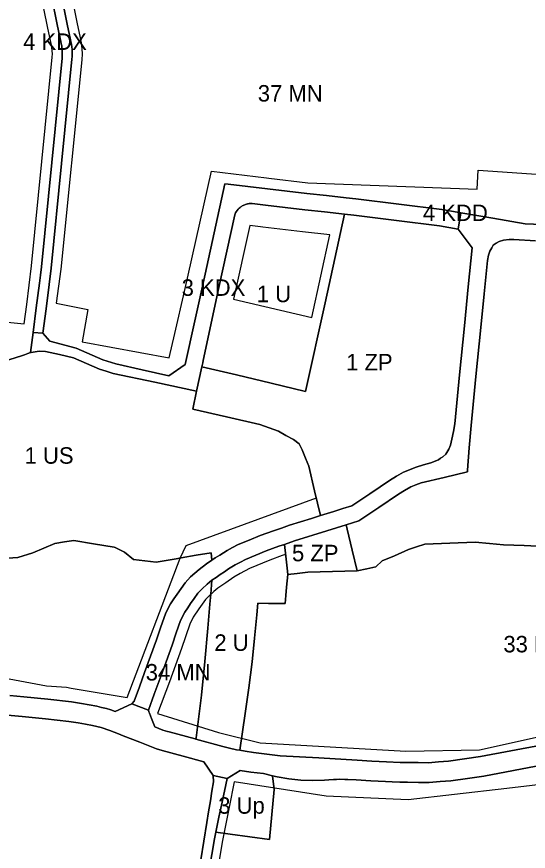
# Model space of a CAD drawing. Extents: x 7423432 to 7425824, y 5537848 to 5539677.
# Drawn here: x 7424531 to 7424841, y 5538619 to 5539125 of the extents above; entities that cross this region are included whole.
import ezdxf

# ---------------------------------------------------------------- set-up
doc = ezdxf.new("R2010")
doc.units = 0
for name, color, linetype in [('linie_rozgraniczajace', 7, 'Continuous'), ('linie_zabudowy_nieprzekraczalne', 7, 'Continuous'), ('oznaczenia_przeznaczen', 7, 'Continuous')]:
    doc.layers.add(name, color=color, linetype=linetype)

msp = doc.modelspace()

# ---------------------------------------------------------------- linework, layer by layer
at = {"layer": 'linie_rozgraniczajace'}
for points in [[(7424557.72, 5539139.78), (7424561.59, 5539120.6), (7424563.62, 5539111.18), (7424564.15, 5539108.31), (7424564.31, 5539106.77), (7424564.48, 5539105.23), (7424564.54, 5539103.9), (7424564.59, 5539102.57), (7424564.52, 5539100.96), (7424564.45, 5539099.35), (7424558.13, 5539035.99), (7424551.8, 5538972.62), (7424550.63, 5538962.66), (7424548.74, 5538947.91), (7424546.85, 5538933.16), (7424540.84, 5538933.51), (7424542.76, 5538948.45), (7424544.68, 5538963.39), (7424545.26, 5538968.36), (7424545.85, 5538973.33), (7424558.49, 5539100.07), (7424558.59, 5539102.66), (7424558.49, 5539104.79), (7424558.21, 5539107.44), (7424557.97, 5539108.72), (7424557.73, 5539110), (7424555.72, 5539119.38), (7424551.85, 5539138.56)], [(7424551.85, 5539138.56), (7424555.72, 5539119.38), (7424557.73, 5539110), (7424557.97, 5539108.72), (7424558.21, 5539107.44), (7424558.49, 5539104.79), (7424558.59, 5539102.66), (7424558.49, 5539100.07), (7424545.85, 5538973.33), (7424545.26, 5538968.36)], [(7424546.85, 5538933.16), (7424548.74, 5538947.91), (7424550.63, 5538962.66), (7424551.8, 5538972.62), (7424558.13, 5539035.99), (7424564.45, 5539099.35), (7424564.52, 5539100.96), (7424564.59, 5539102.57), (7424564.54, 5539103.9), (7424564.48, 5539105.23), (7424564.31, 5539106.77), (7424564.15, 5539108.31), (7424563.62, 5539111.18), (7424561.59, 5539120.6), (7424557.72, 5539139.78)], [(7424849.72, 5538998.98), (7424839.61, 5538999.48), (7424820.03, 5539002.8), (7424800.46, 5539006.12), (7424794.76, 5539007.09), (7424789.05, 5539008.06), (7424762.88, 5539011.29), (7424736.7, 5539014.52), (7424730.84, 5539015.25), (7424718.91, 5539016.56), (7424706.98, 5539017.88), (7424683.15, 5539020.68), (7424671.24, 5539022.11), (7424659.33, 5539023.54), (7424657.23, 5539023.79), (7424645.24, 5538968.93), (7424633.26, 5538914.07), (7424623.23, 5538907.09)], [(7424804.53, 5538848.9), (7424790.47, 5538845.55), (7424776.41, 5538842.19), (7424773.26, 5538840.96), (7424770.12, 5538839.73), (7424766.36, 5538837.51), (7424762.6, 5538835.28), (7424750.65, 5538827.26), (7424738.7, 5538819.24), (7424730.99, 5538816.82), (7424719.15, 5538813.1), (7424699.59, 5538806.95), (7424693.42, 5538804.88), (7424690.07, 5538803.76), (7424686.19, 5538802.32), (7424682.31, 5538800.89), (7424676.03, 5538798.33), (7424669.75, 5538795.77), (7424666.68, 5538794.11), (7424663.61, 5538792.44), (7424661.55, 5538791.21), (7424659.5, 5538789.98), (7424656.99, 5538788.29), (7424654.48, 5538786.6), (7424651.93, 5538784.84), (7424649.39, 5538783.08), (7424646.59, 5538780.79), (7424643.52, 5538777.98), (7424640.88, 5538775.19), (7424638.62, 5538772.06), (7424636.47, 5538769.09), (7424634.7, 5538766.38), (7424632.93, 5538763.66), (7424630.37, 5538758.77), (7424627.79, 5538751.21), (7424625.25, 5538743.79), (7424621.59, 5538733.63), (7424617.97, 5538723.61), (7424614.39, 5538713.92), (7424610.81, 5538704.24), (7424600.85, 5538708.15), (7424602.22, 5538709.76), (7424605.4, 5538718.39), (7424608.57, 5538727.03), (7424612.17, 5538737), (7424615.77, 5538746.97), (7424618.46, 5538754.85), (7424621.16, 5538762.73), (7424622.72, 5538765.73), (7424624.29, 5538768.72), (7424626.26, 5538771.74), (7424628.22, 5538774.75), (7424630.7, 5538778.17), (7424633.17, 5538781.59), (7424636.5, 5538785.11), (7424641.7, 5538789.71), (7424646.06, 5538792.98), (7424649.39, 5538795.3), (7424651.45, 5538796.66), (7424654.13, 5538798.42), (7424658.66, 5538801.13), (7424661.99, 5538802.94), (7424665.32, 5538804.75), (7424672, 5538807.48), (7424678.69, 5538810.21), (7424682.72, 5538811.7), (7424686.75, 5538813.19), (7424691.62, 5538814.82), (7424696.5, 5538816.46), (7424709.95, 5538820.69), (7424715.41, 5538822.4), (7424723.4, 5538824.91), (7424728.86, 5538826.63), (7424734.33, 5538828.35), (7424739.76, 5538832), (7424745.18, 5538835.66), (7424751.48, 5538839.87), (7424757.26, 5538843.74), (7424761.49, 5538846.25), (7424765.72, 5538848.75), (7424773.41, 5538851.76), (7424777.9, 5538853.09), (7424782.39, 5538854.43), (7424786.87, 5538856.19), (7424788.28, 5538857.14), (7424789.68, 5538858.1), (7424791.42, 5538859.65), (7424793.33, 5538862.62), (7424794.25, 5538865), (7424795.16, 5538868.67), (7424795.98, 5538873.32), (7424796.79, 5538877.96), (7424799.74, 5538907.7), (7424802.69, 5538937.44), (7424805.04, 5538961.17), (7424807.39, 5538984.91), (7424799, 5538996.25), (7424800.46, 5539006.12), (7424820.03, 5539002.8), (7424839.61, 5538999.48)], [(7424839.61, 5538999.48), (7424849.72, 5538998.98)], [(7424851.33, 5538803.62), (7424838.93, 5538804.14), (7424826.52, 5538804.66), (7424817.83, 5538805.4), (7424809.13, 5538806.14), (7424793.85, 5538805.62), (7424778.58, 5538805.11), (7424773.68, 5538803.42), (7424768.78, 5538801.73), (7424760.22, 5538797.86), (7424752.7, 5538794.88), (7424748.9, 5538791.18), (7424743.37, 5538790), (7424737.5, 5538788.74), (7424734.55, 5538801.44), (7424731.61, 5538814.15), (7424730.99, 5538816.82), (7424738.7, 5538819.24), (7424750.65, 5538827.26), (7424762.6, 5538835.28), (7424766.36, 5538837.51), (7424770.12, 5538839.73), (7424773.26, 5538840.96), (7424776.41, 5538842.19), (7424790.47, 5538845.55), (7424804.53, 5538848.9), (7424804.53, 5538849.85), (7424805.64, 5538863.46), (7424806.75, 5538877.06), (7424809.69, 5538906.76), (7424812.64, 5538936.45), (7424814.66, 5538956.85), (7424816.68, 5538977.25), (7424817.35, 5538980.5), (7424818.13, 5538982.75), (7424819.28, 5538984.96), (7424820.24, 5538986.38), (7424821.95, 5538987.79), (7424823.76, 5538988.8), (7424826.49, 5538989.53), (7424829.85, 5538989.89), (7424831.25, 5538989.87), (7424832.64, 5538989.85), (7424845.95, 5538989.12)], [(7424845.95, 5538989.12), (7424832.64, 5538989.85), (7424831.25, 5538989.87), (7424829.85, 5538989.89), (7424826.49, 5538989.53), (7424823.76, 5538988.8), (7424821.95, 5538987.79), (7424820.24, 5538986.38), (7424819.28, 5538984.96), (7424818.13, 5538982.75), (7424817.35, 5538980.5), (7424816.68, 5538977.25), (7424814.66, 5538956.85), (7424812.64, 5538936.45), (7424809.69, 5538906.76), (7424806.75, 5538877.06), (7424805.64, 5538863.46), (7424804.53, 5538849.85), (7424804.53, 5538848.9)], [(7424545.26, 5538968.36), (7424544.68, 5538963.39), (7424542.76, 5538948.45), (7424540.84, 5538933.51), (7424539.27, 5538921.25), (7424537.6, 5538920.64), (7424535.58, 5538919.91), (7424533.84, 5538919.37), (7424518.78, 5538914.58)], [(7424623.23, 5538907.09), (7424607.13, 5538910.78), (7424591.03, 5538914.47), (7424583.19, 5538916.87), (7424567.01, 5538924.01), (7424551.05, 5538928.12), (7424546.85, 5538933.16)], [(7424518.78, 5538914.58), (7424533.84, 5538919.37), (7424535.58, 5538919.91), (7424537.6, 5538920.64), (7424539.27, 5538921.25), (7424539.62, 5538921.38), (7424544.6, 5538922.22), (7424548.43, 5538922.03), (7424556.92, 5538920.09), (7424565.42, 5538918.16), (7424573.26, 5538914.7), (7424581.1, 5538911.24), (7424585.29, 5538909.95), (7424589.48, 5538908.67), (7424614.78, 5538903.28), (7424640.08, 5538897.9), (7424637.89, 5538886.94), (7424658.18, 5538882.26), (7424678.47, 5538877.57), (7424689.8, 5538873.51), (7424694.37, 5538871.02), (7424698.95, 5538868.53), (7424702.29, 5538865.92), (7424704.22, 5538862.19), (7424706.19, 5538857.26), (7424708.16, 5538852.32), (7424711.78, 5538837.36), (7424715.41, 5538822.4), (7424709.95, 5538820.69), (7424696.5, 5538816.46), (7424691.62, 5538814.82), (7424686.75, 5538813.19), (7424682.72, 5538811.7), (7424678.69, 5538810.21), (7424672, 5538807.48), (7424665.32, 5538804.75), (7424661.99, 5538802.94), (7424658.66, 5538801.13), (7424654.13, 5538798.42), (7424651.45, 5538796.66), (7424649.39, 5538795.3), (7424648.95, 5538799.85), (7424639.8, 5538798.25), (7424630.66, 5538796.65), (7424627.78, 5538796.14), (7424621.68, 5538795.07), (7424615.59, 5538794.01), (7424601.77, 5538795.73), (7424596.31, 5538800.25), (7424590.66, 5538803), (7424590.05, 5538803.11), (7424577.54, 5538805.26), (7424565.64, 5538807.31), (7424559.87, 5538806.4), (7424554.1, 5538805.49), (7424547.38, 5538802.66), (7424540.67, 5538799.82), (7424531.66, 5538796.85), (7424522.56, 5538796.39)], [(7424522.56, 5538796.39), (7424531.66, 5538796.85), (7424540.67, 5538799.82), (7424547.38, 5538802.66), (7424554.1, 5538805.49), (7424559.87, 5538806.4), (7424565.64, 5538807.31), (7424577.54, 5538805.26), (7424590.05, 5538803.11), (7424590.66, 5538803), (7424596.31, 5538800.25), (7424601.77, 5538795.73), (7424615.59, 5538794.01), (7424621.68, 5538795.07), (7424627.78, 5538796.14), (7424630.66, 5538796.65), (7424639.8, 5538798.25), (7424648.95, 5538799.85), (7424649.39, 5538795.3), (7424646.06, 5538792.98), (7424641.7, 5538789.71), (7424636.5, 5538785.11), (7424633.17, 5538781.59), (7424630.7, 5538778.17), (7424628.22, 5538774.75), (7424626.26, 5538771.74), (7424624.29, 5538768.72), (7424622.72, 5538765.73), (7424621.16, 5538762.73), (7424618.46, 5538754.85), (7424615.77, 5538746.97), (7424612.17, 5538737), (7424608.57, 5538727.03), (7424605.4, 5538718.39), (7424602.22, 5538709.76), (7424600.85, 5538708.15), (7424590.71, 5538703.52), (7424588.01, 5538704.37), (7424585.31, 5538705.22), (7424582.41, 5538705.92), (7424579.51, 5538706.62), (7424574.86, 5538707.51), (7424570.21, 5538708.39), (7424564.11, 5538709.35), (7424549.69, 5538710.88), (7424535.27, 5538712.42), (7424526.67, 5538713.19)], [(7424849.26, 5538683.07), (7424830.9, 5538679.6), (7424812.54, 5538676.12), (7424802.83, 5538674.75), (7424793.12, 5538673.38), (7424787.03, 5538672.86), (7424780.94, 5538672.34), (7424774.63, 5538672.41), (7424768.32, 5538672.48), (7424763.75, 5538672.6), (7424755.3, 5538672.88), (7424746.45, 5538673.39), (7424737.59, 5538673.9), (7424714.22, 5538675.27), (7424690.85, 5538676.65), (7424682.79, 5538677.59), (7424674.73, 5538678.53), (7424669.53, 5538679.4), (7424666.33, 5538679.93), (7424668, 5538691.04), (7424669.67, 5538702.15), (7424671.79, 5538717.86), (7424673.91, 5538733.57), (7424675.34, 5538747.88), (7424676.77, 5538762.2), (7424677.29, 5538769.17), (7424683.76, 5538769.06), (7424690.23, 5538768.95), (7424693.97, 5538768.97), (7424694.34, 5538773.91), (7424694.72, 5538778.86), (7424695.07, 5538782.76), (7424695.42, 5538786.67), (7424701.23, 5538787.21), (7424707.58, 5538788), (7424722.54, 5538788.37), (7424737.5, 5538788.74), (7424743.37, 5538790), (7424748.9, 5538791.18), (7424752.7, 5538794.88), (7424760.22, 5538797.86), (7424768.78, 5538801.73), (7424773.68, 5538803.42), (7424778.58, 5538805.11), (7424793.85, 5538805.62), (7424809.13, 5538806.14), (7424817.83, 5538805.4), (7424826.52, 5538804.66), (7424838.93, 5538804.14), (7424851.33, 5538803.62)], [(7424526.67, 5538713.19), (7424535.27, 5538712.42), (7424549.69, 5538710.88), (7424564.11, 5538709.35), (7424570.21, 5538708.39), (7424574.86, 5538707.51), (7424579.51, 5538706.62), (7424582.41, 5538705.92), (7424585.31, 5538705.22), (7424588.01, 5538704.37), (7424590.71, 5538703.52), (7424600.85, 5538708.15), (7424610.81, 5538704.24), (7424611.18, 5538703.29), (7424611.55, 5538702.36), (7424612.8, 5538699.17), (7424614.8, 5538694.1), (7424617.23, 5538693.16), (7424619.66, 5538692.22), (7424622.49, 5538691.37), (7424623.41, 5538691.12), (7424639.26, 5538686.77), (7424639.7, 5538686.65), (7424656.03, 5538682.17), (7424660.18, 5538681.22), (7424664.32, 5538680.27), (7424666.33, 5538679.93), (7424669.53, 5538679.4), (7424674.73, 5538678.53), (7424682.79, 5538677.59), (7424690.85, 5538676.65), (7424714.22, 5538675.27), (7424737.59, 5538673.9), (7424746.45, 5538673.39), (7424755.3, 5538672.88), (7424763.75, 5538672.6), (7424768.32, 5538672.48), (7424774.63, 5538672.41), (7424780.94, 5538672.34), (7424787.03, 5538672.86), (7424793.12, 5538673.38), (7424802.83, 5538674.75), (7424812.54, 5538676.12), (7424830.9, 5538679.6), (7424849.26, 5538683.07)], [(7424525.3, 5538701.26), (7424534.11, 5538700.48), (7424548.33, 5538698.96), (7424562.55, 5538697.45), (7424565.36, 5538697.01), (7424568.16, 5538696.57), (7424572.57, 5538695.73), (7424576.98, 5538694.89), (7424582.09, 5538693.65), (7424587.36, 5538691.99), (7424592.63, 5538689.91), (7424595.62, 5538688.65), (7424605.69, 5538684.76), (7424615.77, 5538680.86), (7424619.27, 5538679.81), (7424631.89, 5538676.35), (7424644.51, 5538672.88), (7424650.11, 5538664.59), (7424650.31, 5538660.86), (7424649.4, 5538655.1), (7424648.48, 5538649.33), (7424647.43, 5538642.66), (7424646.37, 5538635.99), (7424642.67, 5538613.52)], [(7424850.58, 5538671.12), (7424832.54, 5538667.7), (7424814.5, 5538664.28), (7424804.48, 5538662.86), (7424794.46, 5538661.45), (7424787.92, 5538660.89), (7424781.38, 5538660.34), (7424774.74, 5538660.41), (7424768.09, 5538660.48), (7424763.44, 5538660.61), (7424758.78, 5538660.73), (7424754.71, 5538660.9), (7424745.81, 5538661.41), (7424736.9, 5538661.92), (7424731.94, 5538662.12), (7424730.05, 5538662.19), (7424726.98, 5538662.32), (7424725.09, 5538662.28), (7424723.2, 5538662.25), (7424720.46, 5538662.04), (7424717.72, 5538661.83), (7424710.46, 5538661.58), (7424703.32, 5538661.88), (7424696.2, 5538662.64), (7424689.01, 5538663.78), (7424686.21, 5538664.45), (7424680.82, 5538665.74), (7424676.94, 5538666.19), (7424673.05, 5538666.65), (7424666.49, 5538667.74), (7424658.71, 5538662.84), (7424650.11, 5538664.59), (7424644.51, 5538672.88), (7424631.89, 5538676.35), (7424619.27, 5538679.81), (7424615.77, 5538680.86), (7424605.69, 5538684.76), (7424595.62, 5538688.65), (7424592.63, 5538689.91), (7424587.36, 5538691.99), (7424582.09, 5538693.65), (7424576.98, 5538694.89), (7424572.57, 5538695.73), (7424568.16, 5538696.57), (7424565.36, 5538697.01), (7424562.55, 5538697.45), (7424548.33, 5538698.96), (7424534.11, 5538700.48), (7424525.3, 5538701.26)], [(7424647.39, 5538605.16), (7424649.88, 5538620.13), (7424650.84, 5538625.17), (7424651.8, 5538630.2), (7424660.47, 5538629.05), (7424672.43, 5538627.46), (7424684.39, 5538625.87), (7424685.82, 5538641.04), (7424687.25, 5538656.21), (7424686.21, 5538664.45), (7424689.01, 5538663.78), (7424696.2, 5538662.64), (7424703.32, 5538661.88), (7424710.46, 5538661.58), (7424717.72, 5538661.83), (7424720.46, 5538662.04), (7424723.2, 5538662.25), (7424725.09, 5538662.28), (7424726.98, 5538662.32), (7424730.05, 5538662.19), (7424731.94, 5538662.12), (7424736.9, 5538661.92), (7424745.81, 5538661.41), (7424754.71, 5538660.9), (7424758.78, 5538660.73), (7424763.44, 5538660.61), (7424768.09, 5538660.48), (7424774.74, 5538660.41), (7424781.38, 5538660.34), (7424787.92, 5538660.89), (7424794.46, 5538661.45), (7424804.48, 5538662.86), (7424814.5, 5538664.28), (7424832.54, 5538667.7), (7424850.58, 5538671.12)], [(7424642.67, 5538613.52), (7424646.37, 5538635.99), (7424647.43, 5538642.66), (7424648.48, 5538649.33), (7424649.4, 5538655.1), (7424650.31, 5538660.86), (7424650.11, 5538664.59), (7424658.71, 5538662.84), (7424655.61, 5538648.37), (7424653.7, 5538639.28), (7424651.8, 5538630.2), (7424650.84, 5538625.17), (7424649.88, 5538620.13), (7424647.39, 5538605.16)]]:
    msp.add_lwpolyline(points, dxfattribs=at)
for points in [[(7424539.27, 5538921.25), (7424540.84, 5538933.51), (7424546.85, 5538933.16), (7424551.05, 5538928.12), (7424567.01, 5538924.01), (7424583.19, 5538916.87), (7424591.03, 5538914.47), (7424607.13, 5538910.78), (7424623.23, 5538907.09), (7424633.26, 5538914.07), (7424645.24, 5538968.93), (7424657.23, 5539023.79), (7424659.33, 5539023.54), (7424671.24, 5539022.11), (7424683.15, 5539020.68), (7424706.98, 5539017.88), (7424718.91, 5539016.56), (7424730.84, 5539015.25), (7424736.7, 5539014.52), (7424762.88, 5539011.29), (7424789.05, 5539008.06), (7424794.76, 5539007.09), (7424800.46, 5539006.12), (7424799, 5538996.25), (7424787.6, 5538998.16), (7424761.54, 5539001.38), (7424735.48, 5539004.59), (7424729.83, 5539005.3), (7424717.76, 5539006.63), (7424705.85, 5539007.94), (7424693.91, 5539009.35), (7424681.97, 5539010.75), (7424678.71, 5539011.14), (7424673.75, 5539011.74), (7424673.24, 5539011.74), (7424672.61, 5539011.72), (7424672, 5539011.67), (7424671.49, 5539011.59), (7424670.95, 5539011.49), (7424670.41, 5539011.35), (7424669.81, 5539011.17), (7424669.38, 5539011.01), (7424668.79, 5539010.76), (7424668.33, 5539010.54), (7424667.86, 5539010.28), (7424667.41, 5539010.01), (7424666.97, 5539009.71), (7424666.53, 5539009.38), (7424665.95, 5539008.88), (7424665.4, 5539008.33), (7424664.71, 5539007.53), (7424664.12, 5539006.7), (7424663.82, 5539006.2), (7424663.34, 5539004.91), (7424653.69, 5538960.73), (7424644.04, 5538916.56), (7424643.82, 5538915.08), (7424643.31, 5538912.71), (7424640.08, 5538897.9), (7424614.78, 5538903.28), (7424589.48, 5538908.67), (7424585.29, 5538909.95), (7424581.1, 5538911.24), (7424573.26, 5538914.7), (7424565.42, 5538918.16), (7424556.92, 5538920.09), (7424548.43, 5538922.03), (7424544.6, 5538922.22), (7424539.62, 5538921.38)], [(7424643.31, 5538912.71), (7424643.82, 5538915.08), (7424644.04, 5538916.56), (7424653.69, 5538960.73), (7424663.34, 5539004.91), (7424663.82, 5539006.2), (7424664.12, 5539006.7), (7424664.71, 5539007.53), (7424665.4, 5539008.33), (7424665.95, 5539008.88), (7424666.53, 5539009.38), (7424666.97, 5539009.71), (7424667.41, 5539010.01), (7424667.86, 5539010.28), (7424668.33, 5539010.54), (7424668.79, 5539010.76), (7424669.38, 5539011.01), (7424669.81, 5539011.17), (7424670.41, 5539011.35), (7424670.95, 5539011.49), (7424671.49, 5539011.59), (7424672, 5539011.67), (7424672.61, 5539011.72), (7424673.24, 5539011.74), (7424673.75, 5539011.74), (7424678.71, 5539011.14), (7424681.97, 5539010.75), (7424693.91, 5539009.35), (7424705.85, 5539007.94), (7424717.76, 5539006.63), (7424729.83, 5539005.3), (7424718.07, 5538951.5), (7424706.31, 5538897.69), (7424685.34, 5538902.69), (7424664.37, 5538907.69), (7424653.84, 5538910.2)], [(7424637.89, 5538886.94), (7424640.08, 5538897.9), (7424643.31, 5538912.71), (7424653.84, 5538910.2), (7424664.37, 5538907.69), (7424685.34, 5538902.69), (7424706.31, 5538897.69), (7424718.07, 5538951.5), (7424729.83, 5539005.3), (7424735.48, 5539004.59), (7424761.54, 5539001.38), (7424787.6, 5538998.16), (7424799, 5538996.25), (7424807.39, 5538984.91), (7424805.04, 5538961.17), (7424802.69, 5538937.44), (7424799.74, 5538907.7), (7424796.79, 5538877.96), (7424795.98, 5538873.32), (7424795.16, 5538868.67), (7424794.25, 5538865), (7424793.33, 5538862.62), (7424791.42, 5538859.65), (7424789.68, 5538858.1), (7424788.28, 5538857.14), (7424786.87, 5538856.19), (7424782.39, 5538854.43), (7424777.9, 5538853.09), (7424773.41, 5538851.76), (7424765.72, 5538848.75), (7424761.49, 5538846.25), (7424757.26, 5538843.74), (7424751.48, 5538839.87), (7424745.18, 5538835.66), (7424739.76, 5538832), (7424734.33, 5538828.35), (7424728.86, 5538826.63), (7424723.4, 5538824.91), (7424715.41, 5538822.4), (7424711.78, 5538837.36), (7424708.16, 5538852.32), (7424706.19, 5538857.26), (7424704.22, 5538862.19), (7424702.29, 5538865.92), (7424698.95, 5538868.53), (7424694.37, 5538871.02), (7424689.8, 5538873.51), (7424678.47, 5538877.57), (7424658.18, 5538882.26)], [(7424693.42, 5538804.88), (7424699.59, 5538806.95), (7424719.15, 5538813.1), (7424730.99, 5538816.82), (7424731.61, 5538814.15), (7424734.55, 5538801.44), (7424737.5, 5538788.74), (7424722.54, 5538788.37), (7424707.58, 5538788), (7424701.23, 5538787.21), (7424695.42, 5538786.67), (7424695.07, 5538790.42), (7424694.24, 5538797.65)], [(7424639.7, 5538686.65), (7424639.94, 5538687.57), (7424641.52, 5538700.52), (7424643.1, 5538713.46), (7424645.03, 5538733.75), (7424646.96, 5538754.04), (7424648.17, 5538768.56), (7424648.69, 5538774.67), (7424649.39, 5538783.08), (7424651.93, 5538784.84), (7424654.48, 5538786.6), (7424656.99, 5538788.29), (7424659.5, 5538789.98), (7424661.55, 5538791.21), (7424663.61, 5538792.44), (7424666.68, 5538794.11), (7424669.75, 5538795.77), (7424676.03, 5538798.33), (7424682.31, 5538800.89), (7424686.19, 5538802.32), (7424690.07, 5538803.76), (7424693.42, 5538804.88), (7424694.24, 5538797.65), (7424695.07, 5538790.42), (7424695.42, 5538786.67), (7424695.07, 5538782.76), (7424694.72, 5538778.86), (7424694.34, 5538773.91), (7424693.97, 5538768.97), (7424690.23, 5538768.95), (7424683.76, 5538769.06), (7424677.29, 5538769.17), (7424676.77, 5538762.2), (7424675.34, 5538747.88), (7424673.91, 5538733.57), (7424671.79, 5538717.86), (7424669.67, 5538702.15), (7424668, 5538691.04), (7424666.33, 5538679.93), (7424664.32, 5538680.27), (7424660.18, 5538681.22), (7424656.03, 5538682.17)], [(7424610.81, 5538704.24), (7424614.39, 5538713.92), (7424617.97, 5538723.61), (7424621.59, 5538733.63), (7424625.25, 5538743.79), (7424627.79, 5538751.21), (7424630.37, 5538758.77), (7424632.93, 5538763.66), (7424634.7, 5538766.38), (7424636.47, 5538769.09), (7424638.62, 5538772.06), (7424640.88, 5538775.19), (7424643.52, 5538777.98), (7424646.59, 5538780.79), (7424649.39, 5538783.08), (7424648.69, 5538774.67), (7424648.17, 5538768.56), (7424646.96, 5538754.04), (7424645.03, 5538733.75), (7424643.1, 5538713.46), (7424641.52, 5538700.52), (7424639.94, 5538687.57), (7424639.7, 5538686.65), (7424639.26, 5538686.77), (7424623.41, 5538691.12), (7424622.49, 5538691.37), (7424619.66, 5538692.22), (7424617.23, 5538693.16), (7424614.8, 5538694.1), (7424612.8, 5538699.17), (7424611.55, 5538702.36), (7424611.18, 5538703.29)], [(7424651.8, 5538630.2), (7424653.7, 5538639.28), (7424655.61, 5538648.37), (7424658.71, 5538662.84), (7424666.49, 5538667.74), (7424673.05, 5538666.65), (7424676.94, 5538666.19), (7424680.82, 5538665.74), (7424686.21, 5538664.45), (7424687.25, 5538656.21), (7424685.82, 5538641.04), (7424684.39, 5538625.87), (7424672.43, 5538627.46), (7424660.47, 5538629.05)]]:
    msp.add_lwpolyline(points, close=True, dxfattribs=at)
at = {"layer": 'linie_zabudowy_nieprzekraczalne'}
for points in [[(7424559.78, 5539160.29), (7424567.47, 5539121.83), (7424569.5, 5539112.35), (7424570.09, 5539109.18), (7424570.47, 5539105.68), (7424570.59, 5539102.56), (7424570.43, 5539098.92), (7424557.77, 5538971.98), (7424554.79, 5538951.28), (7424574.14, 5538947.47), (7424570.55, 5538927.76), (7424623.46, 5538918.05), (7424626.88, 5538932.9), (7424632.76, 5538958.39), (7424649.16, 5539031.44), (7424682.52, 5539027.31), (7424683.92, 5539027.14), (7424707.72, 5539024.34), (7424810.45, 5539020.38), (7424811.07, 5539032.07), (7424860.94, 5539028.52)], [(7424537.11, 5538950.46), (7424539.88, 5538973.97), (7424552.5, 5539100.49), (7424552.58, 5539102.55), (7424552.51, 5539104.34), (7424552.27, 5539106.58), (7424551.85, 5539108.83), (7424549.84, 5539118.15), (7424542.59, 5539154.11)], [(7424720.93, 5538992.7), (7424704.32, 5538994.53), (7424680.38, 5538997.35), (7424678.89, 5538997.53), (7424672.47, 5538998.32), (7424662.46, 5538953.71), (7424662.46, 5538953.71), (7424710, 5538942.66), (7424720.93, 5538992.7)], [(7424396.24, 5538940.22), (7424483.37, 5538921.07), (7424492.31, 5538920.3), (7424513.28, 5538926.25), (7424515.12, 5538940.69), (7424535.43, 5538938.68), (7424537.11, 5538950.46)], [(7424478.49, 5538732.19), (7424549.03, 5538719.03), (7424561.05, 5538718.14), (7424564, 5538717.62), (7424564, 5538717.62), (7424564, 5538717.62), (7424597.87, 5538711.87), (7424630.22, 5538796.57), (7424633.8, 5538804.3), (7424712.83, 5538833.06)], [(7424694.11, 5538798.78), (7424692.07, 5538798.1), (7424684.48, 5538795.29), (7424672.32, 5538790.34), (7424666.58, 5538787.23), (7424662.71, 5538784.91), (7424657.86, 5538781.64), (7424653.01, 5538778.29), (7424650.52, 5538776.25), (7424647.72, 5538773.69), (7424645.51, 5538771.36), (7424641.41, 5538765.69), (7424638.11, 5538760.63), (7424635.9, 5538756.4), (7424630.87, 5538741.66), (7424623.6, 5538721.55), (7424616.43, 5538702.16), (7424653.49, 5538690.72), (7424678.77, 5538684.34), (7424767.05, 5538679.35), (7424811.89, 5538680.1), (7424851.02, 5538688.99)], [(7424936.2, 5538669.42), (7424828.41, 5538656.64), (7424796.75, 5538653.06), (7424768.63, 5538649.81), (7424718.73, 5538652.01), (7424662.89, 5538660.81), (7424659.88, 5538645.33), (7424655.62, 5538624.25), (7424655.62, 5538624.25), (7424650.44, 5538592.49)]]:
    msp.add_lwpolyline(points, dxfattribs=at)

# ---------------------------------------------------------------- texts
at = {"layer": 'oznaczenia_przeznaczen'}
for s, p in [('4 KDX', (7424534.78, 5539105)), ('37 MN', (7424677.26, 5539073.65)), ('4 KDD', (7424777.51, 5539001.12)), ('3 KDX', (7424631.03, 5538955.73)), ('1 U', (7424676.65, 5538951.88)), ('1 ZP', (7424730.88, 5538910.46)), ('1 US', (7424535.7, 5538853.83)), ('5 ZP', (7424698.03, 5538794.62)), ('2 U', (7424650.88, 5538740.27)), ('33 MN', (7424826.37, 5538739.34)), ('34 MN', (7424609.2, 5538722.28)), ('3 Up', (7424653.25, 5538641.42))]:
    msp.add_text(s, height=10, dxfattribs=at).set_placement(p)

doc.saveas('drawing.dxf')
